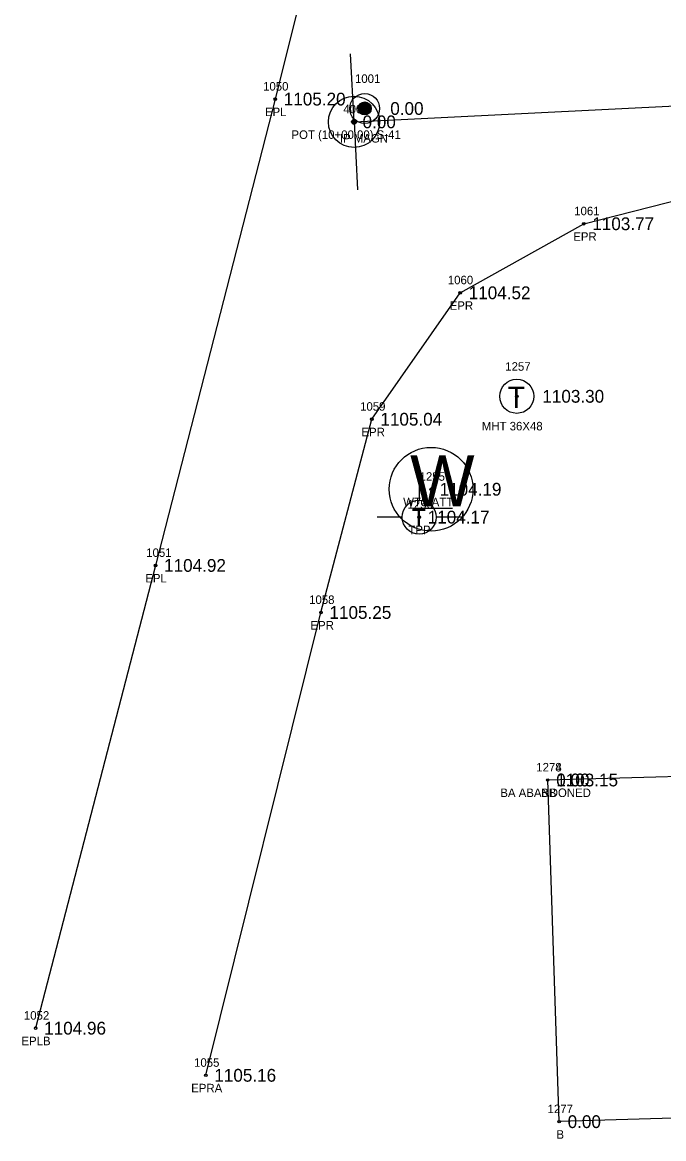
# Model space of a CAD drawing. Extents: x 1539151 to 1541799, y 1198646 to 1201165.
# Drawn here: x 1539354.6 to 1539429.9, y 1199231.1 to 1199362.1 of the extents above; entities that cross this region are included whole.
import ezdxf

# ---------------------------------------------------------------- set-up
doc = ezdxf.new("R2010")
doc.units = 0
for name, color, linetype in [('RD_EX_Bldg', 7, 'Continuous'), ('RD_EX_Bldg_txCode', 7, 'Continuous'), ('RD_EX_DV_Prop_txCode', 7, 'Continuous'), ('RD_EX_DV_PropPin', 7, 'Continuous'), ('RD_EX_Road', 7, 'Continuous'), ('RD_EX_Road_txCode', 7, 'Continuous'), ('RD_EX_SU_Telecom', 7, 'Continuous'), ('RD_EX_TX_Bldg_ELEV', 7, 'Continuous'), ('RD_EX_TX_DV_Prop_ELEV', 7, 'Continuous'), ('RD_EX_TX_Road_ELEV', 7, 'Continuous'), ('RD_EX_TX_UT_ELEV', 7, 'Continuous'), ('RD_EX_UT', 7, 'Continuous'), ('RD_EX_UT_txCode', 7, 'Continuous'), ('RD_HC_Cl', 7, 'Continuous'), ('RD_HC_Data', 7, 'Continuous'), ('RD_HC_Data_Tic', 7, 'Continuous'), ('RD_HC_Survey_ELEV', 7, 'Continuous'), ('RD_HC_txCode', 7, 'Continuous'), ('RD_SMD_Locator', 7, 'Continuous')]:
    doc.layers.add(name, color=color, linetype=linetype)

msp = doc.modelspace()

# ---------------------------------------------------------------- linework, layer by layer
at = {"layer": 'RD_EX_Bldg'}
msp.add_lwpolyline([(1539416.25, 1199273.16), (1539444.4, 1199273.98), (1539445.73, 1199233.89), (1539417.59, 1199233.06), (1539416.25, 1199273.16)], dxfattribs=at)
at = {"layer": 'RD_EX_DV_PropPin'}
for p, q in [((1539394.19, 1199351.5), (1539394.19, 1199352.45)), ((1539394.22, 1199351.46), (1539394.22, 1199352.49)), ((1539394.26, 1199351.42), (1539394.26, 1199352.52)), ((1539394.29, 1199351.39), (1539394.29, 1199352.55)), ((1539394.33, 1199351.36), (1539394.33, 1199352.58)), ((1539394.36, 1199351.34), (1539394.36, 1199352.61)), ((1539394.4, 1199351.32), (1539394.4, 1199352.63)), ((1539394.43, 1199351.3), (1539394.43, 1199352.65)), ((1539394.47, 1199351.28), (1539394.47, 1199352.66)), ((1539394.5, 1199351.26), (1539394.5, 1199352.68)), ((1539394.54, 1199351.25), (1539394.54, 1199352.69)), ((1539394.57, 1199351.24), (1539394.57, 1199352.7)), ((1539394.61, 1199351.23), (1539394.61, 1199352.71)), ((1539394.64, 1199351.22), (1539394.64, 1199352.72)), ((1539394.68, 1199351.22), (1539394.68, 1199352.73)), ((1539394.71, 1199351.21), (1539394.71, 1199352.73)), ((1539394.75, 1199351.21), (1539394.75, 1199352.73)), ((1539394.78, 1199351.21), (1539394.78, 1199352.73)), ((1539394.82, 1199351.21), (1539394.82, 1199352.73)), ((1539394.85, 1199351.21), (1539394.85, 1199352.73)), ((1539394.89, 1199351.22), (1539394.89, 1199352.73)), ((1539394.92, 1199351.22), (1539394.92, 1199352.72)), ((1539394.96, 1199351.23), (1539394.96, 1199352.71)), ((1539394.99, 1199351.24), (1539394.99, 1199352.7)), ((1539395.03, 1199351.25), (1539395.03, 1199352.69)), ((1539395.06, 1199351.26), (1539395.06, 1199352.68)), ((1539395.1, 1199351.28), (1539395.1, 1199352.66)), ((1539395.13, 1199351.3), (1539395.13, 1199352.65)), ((1539395.17, 1199351.32), (1539395.17, 1199352.63)), ((1539395.2, 1199351.34), (1539395.2, 1199352.61)), ((1539395.24, 1199351.36), (1539395.24, 1199352.58)), ((1539395.27, 1199351.39), (1539395.27, 1199352.55)), ((1539395.31, 1199351.42), (1539395.31, 1199352.52)), ((1539395.34, 1199351.46), (1539395.34, 1199352.49)), ((1539395.38, 1199351.5), (1539395.38, 1199352.45)), ((1539394.05, 1199351.78), (1539394.05, 1199352.17)), ((1539394.08, 1199351.67), (1539394.08, 1199352.27)), ((1539394.12, 1199351.6), (1539394.12, 1199352.34)), ((1539394.15, 1199351.55), (1539394.15, 1199352.4)), ((1539395.41, 1199351.55), (1539395.41, 1199352.4)), ((1539395.45, 1199351.6), (1539395.45, 1199352.34)), ((1539395.48, 1199351.67), (1539395.48, 1199352.27)), ((1539395.52, 1199351.78), (1539395.52, 1199352.17))]:
    msp.add_line(p, q, dxfattribs=at)
for radius in [1.75, 0.761]:
    msp.add_circle((1539394.78, 1199351.97), radius, dxfattribs=at)
at = {"layer": 'RD_EX_Road'}
for points in [[(1539409.02, 1199457.17), (1539397.06, 1199404.32), (1539384.29, 1199353.07), (1539370.25, 1199298.34), (1539356.18, 1199244.03)], [(1539376.14, 1199238.5), (1539389.65, 1199292.82), (1539395.62, 1199315.5), (1539405.98, 1199330.34), (1539420.48, 1199338.44), (1539434.13, 1199341.92), (1539458.27, 1199343.35), (1539505.21, 1199345.92), (1539518.44, 1199346.66), (1539558.02, 1199348.62), (1539607.46, 1199351.19), (1539654.3, 1199353.64), (1539676.57, 1199355), (1539708.42, 1199356.93), (1539757.47, 1199359.08), (1539779.44, 1199360.44), (1539802.8, 1199361.54), (1539858.43, 1199364.46), (1539908.44, 1199366.95), (1539925.86, 1199367.85), (1539963.35, 1199372.53)]]:
    msp.add_lwpolyline(points, dxfattribs=at)
at = {"layer": 'RD_EX_SU_Telecom'}
msp.add_circle((1539412.62, 1199318.19), 2, dxfattribs=at)
at = {"layer": 'RD_EX_UT'}
for p, q in [((1539401.17, 1199309.08), (1539401.17, 1199306.01)), ((1539396.24, 1199304.03), (1539399.17, 1199304.03)), ((1539400.44, 1199305.07), (1539405.07, 1199305.07)), ((1539403.17, 1199304.03), (1539406.24, 1199304.03))]:
    msp.add_line(p, q, dxfattribs=at)
for centre, radius in [((1539402.57, 1199307.28), 4.91), ((1539401.17, 1199304.01), 2)]:
    msp.add_circle(centre, radius, dxfattribs=at)
at = {"layer": 'RD_HC_Cl'}
msp.add_line((1539393.53, 1199350.4), (1539900.86, 1199375.77), dxfattribs=at)
at = {"layer": 'RD_HC_Data'}
for radius in [3, 0.282]:
    msp.add_circle((1539393.53, 1199350.4), radius, dxfattribs=at)
at = {"layer": 'RD_HC_Data_Tic'}
for q in [(1539393.13, 1199358.39), (1539393.93, 1199342.41)]:
    msp.add_line((1539393.53, 1199350.4), q, dxfattribs=at)
at = {"layer": 'RD_SMD_Locator'}
for centre in [(1539384.29, 1199353.07), (1539394.78, 1199351.97), (1539393.53, 1199350.4), (1539420.48, 1199338.44), (1539405.98, 1199330.34), (1539412.62, 1199318.19), (1539395.62, 1199315.5), (1539402.57, 1199307.28), (1539401.17, 1199304.01), (1539370.25, 1199298.34), (1539389.65, 1199292.82), (1539416.25, 1199273.16), (1539416.25, 1199273.16), (1539356.18, 1199244.03), (1539376.14, 1199238.5), (1539417.59, 1199233.06)]:
    msp.add_circle(centre, 0.15, dxfattribs=at)

# ---------------------------------------------------------------- texts
at = {"layer": 'RD_EX_Bldg_txCode'}
for s, p in [('1274', (1539414.91, 1199274.16)), ('1278', (1539414.91, 1199274.16)), ('BA ABANDONED', (1539410.69, 1199271.16)), ('BB', (1539415.47, 1199271.16)), ('1277', (1539416.24, 1199234.06)), ('B', (1539417.28, 1199231.06))]:
    msp.add_text(s, height=1, dxfattribs=at).set_placement(p)
at = {"layer": 'RD_EX_DV_Prop_txCode'}
for s, p in [('1001', (1539393.64, 1199354.97)), ('IP MAGN', (1539391.87, 1199347.97))]:
    msp.add_text(s, height=1, dxfattribs=at).set_placement(p)
at = {"layer": 'RD_EX_Road_txCode'}
for s, p in [('1050', (1539382.86, 1199354.07)), ('EPL', (1539383.08, 1199351.07)), ('1061', (1539419.36, 1199339.44)), ('EPR', (1539419.25, 1199336.44)), ('1060', (1539404.53, 1199331.34)), ('EPR', (1539404.75, 1199328.34)), ('1059', (1539394.24, 1199316.5)), ('EPR', (1539394.4, 1199313.5)), ('1051', (1539369.15, 1199299.34)), ('EPL', (1539369.04, 1199296.34)), ('1058', (1539388.26, 1199293.82)), ('EPR', (1539388.42, 1199290.82)), ('1052', (1539354.8, 1199245.03)), ('EPLB', (1539354.51, 1199242.03)), ('1055', (1539374.76, 1199239.5)), ('EPRA', (1539374.43, 1199236.5))]:
    msp.add_text(s, height=1, dxfattribs=at).set_placement(p)
at = {"layer": 'RD_EX_SU_Telecom'}
msp.add_text('T', height=2.5, dxfattribs=at).set_placement((1539411.56, 1199316.82))
at = {"layer": 'RD_EX_TX_Bldg_ELEV'}
for s, p in [('0.00', (1539417.25, 1199272.41)), ('1103.15', (1539417.25, 1199272.41)), ('0.00', (1539418.59, 1199232.31))]:
    msp.add_text(s, height=1.5, dxfattribs=at).set_placement(p)
at = {"layer": 'RD_EX_TX_DV_Prop_ELEV'}
msp.add_text('0.00', height=1.5, dxfattribs=at).set_placement((1539397.78, 1199351.22))
at = {"layer": 'RD_EX_TX_Road_ELEV'}
for s, p in [('1105.20', (1539385.29, 1199352.32)), ('1103.77', (1539421.48, 1199337.69)), ('1104.52', (1539406.98, 1199329.59)), ('1105.04', (1539396.62, 1199314.75)), ('1104.92', (1539371.25, 1199297.59)), ('1105.25', (1539390.65, 1199292.07)), ('1104.96', (1539357.18, 1199243.28)), ('1105.16', (1539377.14, 1199237.75))]:
    msp.add_text(s, height=1.5, dxfattribs=at).set_placement(p)
at = {"layer": 'RD_EX_TX_UT_ELEV'}
for s, p in [('1103.30', (1539415.62, 1199317.44)), ('1104.19', (1539403.57, 1199306.53)), ('1104.17', (1539402.17, 1199303.26))]:
    msp.add_text(s, height=1.5, dxfattribs=at).set_placement(p)
at = {"layer": 'RD_EX_UT'}
for s, height, p in [('W', 6, (1539400.1, 1199305.28)), ('T', 2, (1539400.32, 1199302.97))]:
    msp.add_text(s, height=height, dxfattribs=at).set_placement(p)
at = {"layer": 'RD_EX_UT_txCode'}
for s, p in [('1257', (1539411.27, 1199321.19)), ('MHT 36X48', (1539408.52, 1199314.19)), ('1255', (1539401.22, 1199308.28)), ('WTS ATT', (1539399.3, 1199305.28)), ('1256', (1539399.8, 1199305.01)), ('TPP', (1539399.9, 1199302.01))]:
    msp.add_text(s, height=1, dxfattribs=at).set_placement(p)
at = {"layer": 'RD_HC_Survey_ELEV'}
msp.add_text('0.00', height=1.5, dxfattribs=at).set_placement((1539394.53, 1199349.65))
at = {"layer": 'RD_HC_txCode'}
for s, p in [('400', (1539392.27, 1199351.4)), ('POT (10+00.00) S-41', (1539386.19, 1199348.4))]:
    msp.add_text(s, height=1, dxfattribs=at).set_placement(p)

doc.saveas('drawing.dxf')
